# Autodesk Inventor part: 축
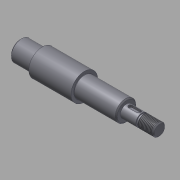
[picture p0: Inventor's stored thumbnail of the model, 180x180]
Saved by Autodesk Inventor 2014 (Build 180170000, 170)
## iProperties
Created: 2015-12
Part Number: 축
Material: 강철, 연강
Document SubType Name: Modeling
Designer: mdu
Density: 7.86 g/cm^3
Mass: 350.729 g
Surface Area: 95.1089 cm^2
Volume: 44.6221 cm^3
Appearance: Steel
CustomPartVersion: 1
Author: mdu
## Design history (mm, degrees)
sketch "스케치5"
  geometry: L1 (0, 0)-(135, 0); L2 (0, 0)-(135, 0); L3 (135, 0)-(135, 6); L4 (103, 6)-(103, 10); L5 (103, 10)-(62, 10); L6 (62, 10)-(62, 13); L7 (62, 13)-(21, 13); L8 (21, 13)-(21, 10); L9 (21, 10)-(0, 10); L10 (0, 10)-(0, 0); L11 (118, 6)-(118, 5); L12 (118, 5)-(120, 5); L13 (120, 5)-(120, 6); L14 (135, 6)-(120, 6); L15 (118, 6)-(103, 6)
  constraints: 31 end point, 12 perpendicular, 9 parallel, 1 collinear, 1 horizontal
  dimensions: "d43" = 20 diameter of L9 L1; "d44" = 26 diameter of L7 L1; "d45" = 20 diameter of L5 L2; "d47" = 41 distance of L6.end L7.end; "d48" = 32 distance between parallel lines of L3 L4; "d50" = 21 distance of L8.end L9.end; "d52" = 12 diameter of L14 L1; "d53" = 15 distance between parallel lines of L3 L13; "d54" = 2 distance of L11.end L12.end; "d55" = 1 distance between parallel lines of L14 L12; "d64" = 135 distance of L1.start L1.end
revolve "회전4" sketch "스케치5" stored, may be unused: angle "d51" = 90 deg
feature "스레드6" dims "d56" = 10, "d57" = 0
chamfer "모따기6" distance "d32" = 1; stored, may be unused: second distance "d33" = 0.4, angle "d34" = 45 deg
chamfer "모따기5" distance "d27" = 1; stored, may be unused: second distance "d28" = 0.125, angle "d29" = 45 deg
fillet "모깎기1" dims "d17" = 0.3
fillet "모깎기2" dims "d18" = 0.3
chamfer "모따기3" distance "d19" = 1; stored, may be unused: second distance "d20" = 1, angle "d21" = 45 deg
node "작업 평면1"
sketch "스케치6"
  geometry: L1 (-3.5, 2)-(4.5, 2); L2 (4.5, -2)-(-3.5, -2); L3 (-7.5, 9)-(-7.5, -9) reference; A1 r 2 centre (4.5, 0) between (4.5, -2) and (4.5, 2); A2 r 2 centre (-3.5, 0) between (-3.5, 2) and (-3.5, -2); 1 further point
  constraints: 4 end point, 4 point on circle, 4 tangent, 2 centre point, 1 horizontal, 1 horizontal alignment, 1 parallel
  dimensions: "d59" = 2 distance edge to line of A2 L3; "d60" = 12 dimension on A1 A2; "d61" = 4 distance between parallel lines of L2 L1
extrude "돌출1" cut sketch "스케치6" distance "d62" = 2.3; taper "d63" = 0 deg
node "솔리드1"
node "솔리드2"
other parameters: "d46" = 12
